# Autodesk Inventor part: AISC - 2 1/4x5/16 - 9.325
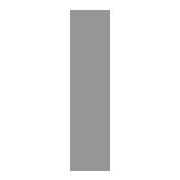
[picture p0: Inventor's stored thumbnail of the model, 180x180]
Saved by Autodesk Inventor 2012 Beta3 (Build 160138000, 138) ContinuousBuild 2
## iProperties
_CCFamilyMember: 149
_CCFamilyDisplayName: ANSI AISC (Rectangular) - Flat Bar Steel
_FrameMemberDoc: Frame Member File
_Version: 15.0.0
_GetPNFromCC: 1
Created: 2010-11
Part Number: AISC - 2 1/4x5/16 - 9.325
Material: Steel, Mild
Description: Flat Bar Steel
Document SubType Name: Modeling
Standard: ANSI
Designer: Beta-8540w
Standards Organization: ANSI
Language: en-US
Size Designation: 2 1/4x5/16
Categories: <MemberInstance><Categories><Category DisplayName="Structural Shapes" InternalName="089c4875-fa83-4c05-b084-43b9cc11f5ed" Mnemonic="GRDR"><CategoryParameter Dis
Stock Number: 2 1/4x5/16
Density: 7.86 g/cm^3
IsCustomPart: 1
G_L: 9.325 in
G_W: 0.313 in
G_H: 2.250 in
Author: Beta-8540w
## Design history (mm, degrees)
node "Start plane"
node "End plane"
node "Driven Length"
  sketch "Sketch3"
    geometry: L1 (0, 0)-(10, 0) reference
    constraints: 2 end point, 1 horizontal
  workplane "Work Plane3"
  sketch "Sketch4"
    geometry: L1 (-2, 0)-(12, 0) reference; L2 (-40.005, 236.864)-(40.005, 236.864) reference
    dimensions: "d9" = 236.86413 distance between parallel lines of L1 L2 (derived)
sketch "Sweep Path"
  geometry: L1 through (25.4, 40.279) direction (-1, 0); L2 through (112.121, 127) direction (-1, 0); 9 other entities
  constraints: 10 horizontal
node "Orientation Work Plane"
feature "Body" dims "d10" = 0
body "Solid1"
sketch "Sketch"
  geometry: L1 (3.969, -28.575)-(-3.969, -28.575); L2 (-3.969, -28.575)-(-3.969, 28.575); L3 (-3.969, 28.575)-(3.969, 28.575); L4 (3.969, 28.575)-(3.969, -28.575); L5 (-6, 0)-(8, 0); L6 (0, -30)-(0, 40); L7 (0, 54)-(0, -44); L8 (-9.2, 0)-(13.2, 0)
  constraints: 16 end point, 2 collinear, 2 parallel, 1 horizontal, 1 perpendicular
  dimensions: "d0" = 57.15 distance between parallel lines of L3 L1 (= G_W); "d1" = 7.9375 distance between parallel lines of L4 L2 (= G_H); "d4" = 3.96875 distance between parallel lines of L6 L4 (= 0.5 x d1); "d5" = 28.575 distance between parallel lines of L5 L3 (= 0.5 x d0)
other parameters: "G_W" = 57.15 [user parameter; used in 1 equation term], "G_H" = 7.9375 [user parameter; used in 1 equation term], "G_L" = 236.86413 (= d9) [user parameter], "G_OFFSET_START" = 0 [user parameter; used in 1 equation term], "G_OFFSET_END" = 0 [user parameter; used in 1 equation term], "d6" = 0 (computed from G_OFFSET_START), "d7" = 236.86413 (= G_OFFSET_END + B_L), "B_L" = 236.86413 [user parameter; used in 1 equation term], "d8" = 90 deg
